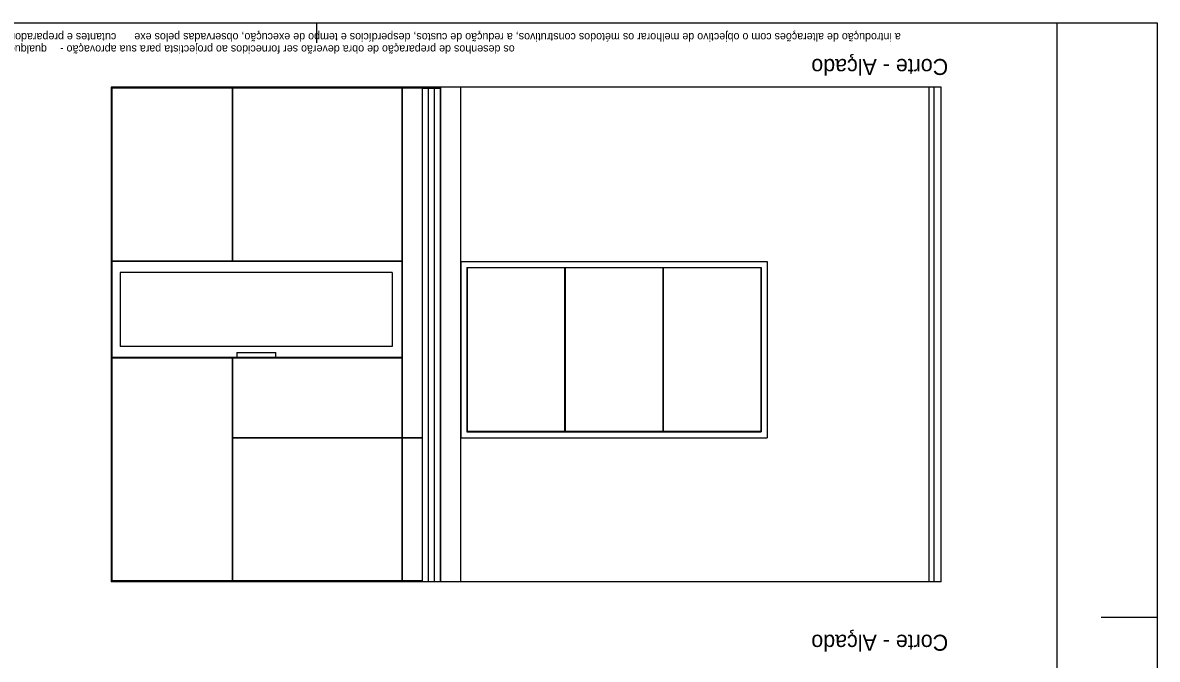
# Model space of a CAD drawing. Extents: x 1306.3 to 1323.2, y -308.3 to -299.9.
# Drawn here: x 1317.51 to 1323.18, y -303.12 to -299.95 of the extents above; entities that cross this region are included whole.
import ezdxf

# ---------------------------------------------------------------- set-up
doc = ezdxf.new("R2010")
doc.units = 0
for name, color, linetype in [('Level 1', 7, 'Continuous'), ('Level 13', 7, 'Continuous'), ('Level 2', 7, 'Continuous'), ('Level 60', 7, 'Continuous'), ('Level 62', 7, 'Continuous')]:
    doc.layers.add(name, color=color, linetype=linetype)

msp = doc.modelspace()

# ---------------------------------------------------------------- linework, layer by layer
at = {"layer": 'Level 1'}
for p, q in [((1322.0966, -300.268), (1317.9505, -300.268)), ((1317.9505, -300.268), (1317.9505, -302.738)), ((1322.0966, -302.738), (1317.9505, -302.738))]:
    msp.add_line(p, q, dxfattribs=at)
at = {"layer": 'Level 13'}
for p, q in [((1318.4225, -300.273), (1317.9505, -300.273)), ((1317.9525, -300.273), (1317.9525, -301.136)), ((1317.9525, -300.273), (1317.9525, -301.618)), ((1319.5046, -300.273), (1318.4245, -300.273)), ((1318.5545, -300.273), (1318.5545, -301.136)), ((1318.5565, -300.273), (1318.5565, -301.136)), ((1319.4025, -300.268), (1319.4025, -301.136)), ((1319.4045, -300.268), (1319.4045, -302.018)), ((1319.5046, -300.273), (1319.5946, -300.273)), ((1319.5046, -300.273), (1319.5046, -302.738)), ((1319.5346, -300.273), (1319.5346, -302.738)), ((1319.5646, -300.273), (1319.5646, -302.738)), ((1319.5946, -300.268), (1319.5946, -302.738)), ((1322.0616, -302.738), (1322.0616, -300.268)), ((1322.0966, -302.738), (1322.0966, -300.268)), ((1318.5545, -301.136), (1317.9525, -301.136)), ((1319.4025, -301.138), (1317.9525, -301.138)), ((1319.4025, -301.136), (1318.5565, -301.136)), ((1319.4025, -301.138), (1319.4025, -301.618)), ((1319.6966, -301.138), (1321.2286, -301.138)), ((1319.6966, -301.138), (1319.6966, -302.018)), ((1321.2286, -301.138), (1321.2286, -302.018)), ((1319.3543, -301.193), (1317.9955, -301.193)), ((1317.9955, -301.193), (1317.9955, -301.563)), ((1319.3543, -301.193), (1319.3543, -301.563)), ((1319.7266, -301.168), (1321.1986, -301.168)), ((1319.7266, -301.168), (1319.7266, -301.988)), ((1321.1966, -301.17), (1319.7286, -301.17)), ((1319.7286, -301.17), (1319.7286, -301.986)), ((1320.2176, -301.986), (1320.2176, -301.17)), ((1320.2196, -301.986), (1320.2196, -301.17)), ((1320.7076, -301.986), (1320.7076, -301.17)), ((1320.7096, -301.986), (1320.7096, -301.17)), ((1321.1966, -301.17), (1321.1966, -301.988)), ((1321.1986, -301.168), (1321.1986, -301.988)), ((1319.3543, -301.563), (1317.9955, -301.563)), ((1318.5774, -301.593), (1318.7724, -301.593)), ((1318.5774, -301.593), (1318.5774, -301.618)), ((1318.7724, -301.618), (1318.7724, -301.593)), ((1319.4025, -301.618), (1317.9525, -301.618)), ((1317.9525, -301.62), (1317.9525, -302.733)), ((1318.5545, -301.62), (1317.9525, -301.62)), ((1318.5545, -301.62), (1318.5545, -302.733)), ((1318.5565, -301.618), (1318.7515, -301.618)), ((1319.4025, -301.62), (1318.5565, -301.62)), ((1318.5565, -301.62), (1318.5565, -302.018)), ((1319.4025, -301.62), (1319.4025, -302.018)), ((1319.7266, -301.988), (1321.1986, -301.988)), ((1319.7286, -301.986), (1321.1986, -301.986)), ((1319.4025, -302.018), (1318.5565, -302.018)), ((1318.5565, -302.02), (1318.5565, -302.733)), ((1319.0485, -302.02), (1318.5565, -302.02)), ((1319.4025, -302.02), (1319.0505, -302.02)), ((1319.4025, -302.02), (1319.4025, -302.733)), ((1319.5046, -302.018), (1319.4045, -302.018)), ((1319.4045, -302.02), (1319.4045, -302.733)), ((1319.5046, -302.02), (1319.4045, -302.02)), ((1319.6966, -302.018), (1321.2286, -302.018)), ((1318.5545, -302.733), (1317.9525, -302.733)), ((1319.4025, -302.733), (1318.5565, -302.733)), ((1319.5046, -302.733), (1319.4045, -302.733))]:
    msp.add_line(p, q, dxfattribs=at)
at = {"layer": 'Level 2'}
for p, q in [((1319.5966, -302.738), (1319.5966, -300.268)), ((1319.6966, -302.738), (1319.6966, -300.268)), ((1322.0366, -302.738), (1322.0366, -300.268))]:
    msp.add_line(p, q, dxfattribs=at)
at = {"layer": 'Level 62'}
for p, q in [((1318.9776, -300.0454), (1318.9776, -299.9454)), ((1322.6772, -308.3454), (1322.6772, -299.9454)), ((1323.1772, -302.9154), (1322.8972, -302.9154))]:
    msp.add_line(p, q, dxfattribs=at)
msp.add_lwpolyline([(1323.1772, -299.9454), (1323.1772, -308.3454), (1311.5776, -308.3454), (1311.5776, -299.9454)], close=True, dxfattribs=at)

# ---------------------------------------------------------------- texts
at = {"layer": 'Level 60'}
for p in [(1322.1323, -300.1264), (1322.1323, -303.0017)]:
    msp.add_text('Corte - Alçado', height=0.08, rotation=180, dxfattribs=at).set_placement(p)
at = {"layer": 'Level 62'}
for s, height, p in [('cutantes e preparadores da obra deverão ser sugeridas. não poderão no entanto ser implementadas sem o consentimento expresso dos responsáveis pela arquitectura', 0.0399996, (1317.9755, -299.9974)), ('a introdução de alterações com o objectivo de melhorar os métodos construtivos, a redução de custos, desperdícios e tempo de execução, observadas pelos exe', 0.0399996, (1321.8953, -299.9974)), ('qualquer discrepancia ou incoerencia detectada deverá ser comunicada aos responsáveis pela arquitectura com o objectivo de ser analizada e corrigida -', 0.0399996, (1317.6289, -300.0584)), ('os desenhos de preparação de obra deverão ser fornecidos ao projectista para sua aprovação -', 0.04, (1319.9663, -300.0584))]:
    msp.add_text(s, height=height, rotation=180, dxfattribs=at).set_placement(p)

doc.saveas('drawing.dxf')
